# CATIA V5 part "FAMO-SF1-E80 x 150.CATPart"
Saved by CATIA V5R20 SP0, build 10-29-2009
Part number: FAMO-SF1-E80 x 150
Definition: NONE
Nomenclature: FAMO-SF1-E80 x 150
Source: Unknown
Description: FAMO-SF1-E80 x 150
Bounding box of the stored display mesh (mm): x -102 to 48, y -55.5 to 55.5, z -55.5 to 55.5
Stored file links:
  C:\Users\Utente\Desktop\IO LAVORO\3D X SITO CF\X SITO\FAMO\FAMO-SF1-E80 x 150.CATPart
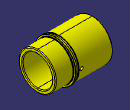
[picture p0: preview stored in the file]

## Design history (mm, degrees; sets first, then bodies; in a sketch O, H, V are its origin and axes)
Body1 "FAMO-SF1-E80 x 150" (main body)
  Solid1: solid without history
